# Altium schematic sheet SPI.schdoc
size 297 x 209 mm; Symbol: Drawing-Symbol_A4; Company: 嘉立创EDA; Version: V1.0; Page Size: A4; @Project Name: 西柚在学EtherCAT; @Update Date: 2026-08-01; @Create Date: 2026-08-01; Device: Drawing-Symbol_A4; @Board Name: HPM5E3YIVK1_2; @Page Name: P1; @Create Time: 18:02:50; @Page Count: 11; @Page No: 11; @Schematic Name: HPM5E3YIVK1_2; @Update Time: 18:02:50; @Assembly Variant: Basic; Border: 1; Title Block Position: 3; Size: A4; Width: 1170; Height: 825; Region Start: 1; X Region Count: 6; Y Region Count: 4; Blade Width: 10
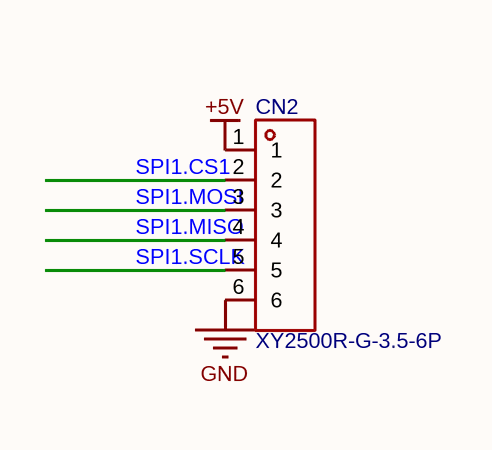
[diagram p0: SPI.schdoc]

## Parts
CN2  XY2500R-G-3.5-6P  [CONN-TH_XY2500R-G-3.5-6P]

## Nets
+5V: CN2.1
GND: CN2.6
SPI1.CS1: CN2.2
SPI1.MISO: CN2.4
SPI1.MOSI: CN2.3
SPI1.SCLK: CN2.5

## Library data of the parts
CN2 = XY2500R-G-3.5-6P: 连接器类型:板端/插座-闭口;结构:1x6P;间距:3.5mm;颜色:绿色;安装方式:弯插;排数:1;每排PIN数:6;额定电流:8A;额定电压:300V;工作温度:-;; Manufacturer: XINLAIYA(新莱亚); 3D Model: 5a543dc2bf4f481394ce0a7ea8dd4c610819f05c4eef4c71ace90d822a990e87; 3D Model Transform: 866.14,358.267,0,0,0,0,0,124.016,-137.795; Number of Positions or Pins: 1x6P; Pitch: 3.5mm; Number of PINs Per Row: 6; Current Rating: 8A; Voltage Rating (Max): 300V; AddInBom: yes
